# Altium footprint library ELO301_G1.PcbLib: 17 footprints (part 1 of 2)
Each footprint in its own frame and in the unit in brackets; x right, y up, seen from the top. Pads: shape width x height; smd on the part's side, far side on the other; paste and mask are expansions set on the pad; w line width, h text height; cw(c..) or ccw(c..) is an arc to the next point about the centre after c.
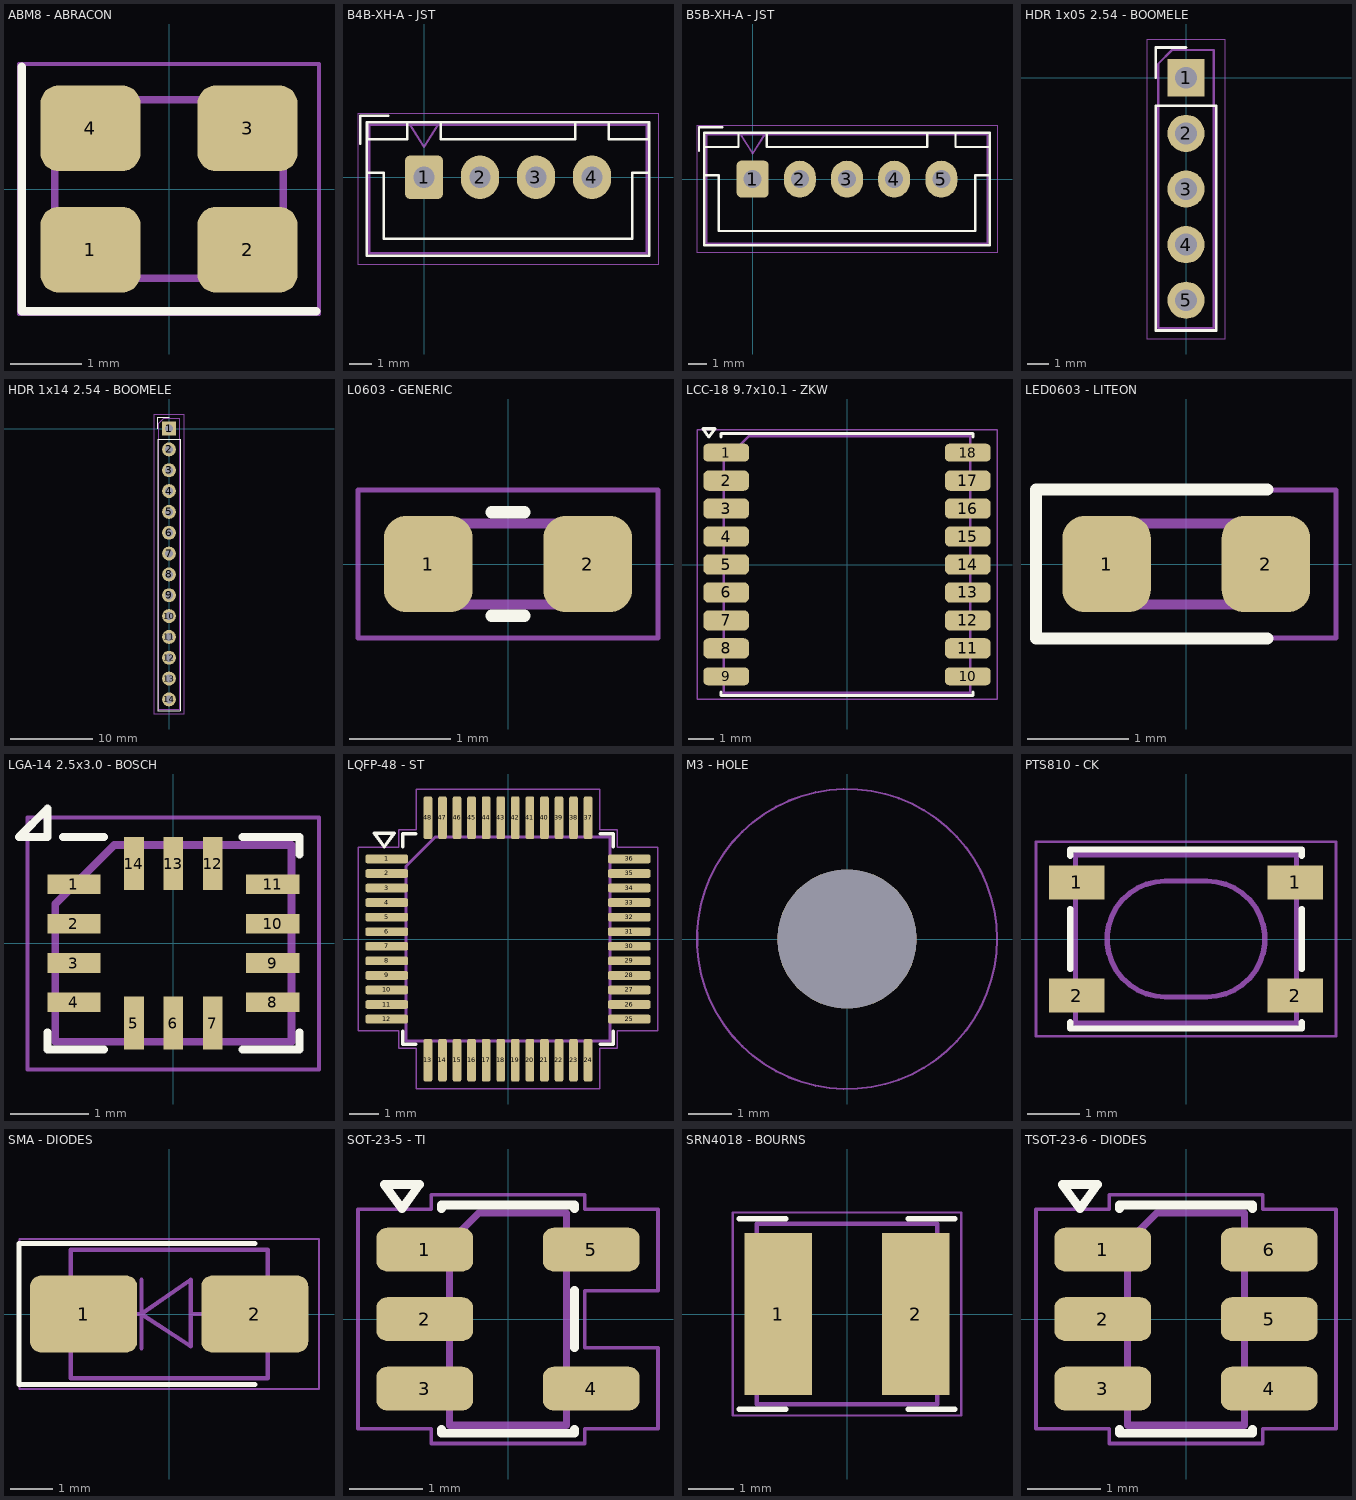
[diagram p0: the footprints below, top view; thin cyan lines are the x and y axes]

## ABM8 - ABRACON [mm] "Abracon ABM8G, Miniature Ceramic Crystal, 3.2x2.5mm package, SMD, http://www.abracon.com/Resonators/ABM8G.pdf"
pads (4):
  rrect42% 1.4x1.2 smd: 1(-1.1,-0.85) 2(1.1,-0.85) 3(1.1,0.85) 4(-1.1,0.85)
Top Overlay:
  lines w0.12: -2.06,1.71 -2.06,-1.71 2.06,-1.71
Mechanical 13:
  lines w0.1: -1.6,-0.625 -0.975,-1.25 1.6,-1.25 1.6,1.25 -1.6,1.25 -1.6,-0.625
Mechanical 15:
  lines w0.05: -2.1,-1.75 2.1,-1.75 2.1,1.75 -2.1,1.75 -2.1,-1.75
Mechanical 29:
  text ".Designator" at -0.508,-0.102 h0.25

## B4B-XH-A - JST [mm] "JST XH series connector, B4B-XH-A (http://www.jst-mfg.com/product/pdf/eng/eXH.pdf)"
pads (4):
  rrect29% 1.7x1.95 hole 0.95: 1(0,0)
  oval 1.7x1.95 hole 0.95: 2(2.5,0) 3(5,0) 4(7.5,0)
Top Overlay:
  lines w0.12: -2.85,1.5 -2.85,2.75 -1.6,2.75 ; -2.55,0.2 -1.8,0.2 -1.8,-2.75 3.75,-2.75 9.3,-2.75 9.3,0.2 10.05,0.2 ; -2.56,-3.51 10.06,-3.51 10.06,2.46 -2.56,2.46 -2.56,-3.51 ; -2.55,1.7 -0.75,1.7 -0.75,2.45 -2.55,2.45 -2.55,1.7 ; 0.75,1.7 6.75,1.7 6.75,2.45 0.75,2.45 0.75,1.7 ; 8.25,1.7 10.05,1.7 10.05,2.45 8.25,2.45 8.25,1.7
Mechanical 13:
  lines w0.1: -0.625,2.35 0,1.35 0.625,2.35 ; -2.45,-3.4 9.95,-3.4 9.95,2.35 -2.45,2.35 -2.45,-3.4
Mechanical 15:
  lines w0.05: -2.95,-3.9 10.45,-3.9 10.45,2.85 -2.95,2.85 -2.95,-3.9
Mechanical 29:
  text ".Designator" at -0.508,-0.102 h0.25

## B5B-XH-A - JST [mm] "JST XH series connector, B5B-XH-A (http://www.jst-mfg.com/product/pdf/eng/eXH.pdf)"
pads (5):
  rrect29% 1.7x1.95 hole 0.95: 1(0,0)
  oval 1.7x1.95 hole 0.95: 2(2.5,0) 3(5,0) 4(7.5,0) 5(10,0)
Top Overlay:
  lines w0.12: -2.85,1.5 -2.85,2.75 -1.6,2.75 ; -2.55,0.2 -1.8,0.2 -1.8,-2.75 5,-2.75 11.8,-2.75 11.8,0.2 12.55,0.2 ; -2.56,-3.51 12.56,-3.51 12.56,2.46 -2.56,2.46 -2.56,-3.51 ; -2.55,1.7 -0.75,1.7 -0.75,2.45 -2.55,2.45 -2.55,1.7 ; 0.75,1.7 9.25,1.7 9.25,2.45 0.75,2.45 0.75,1.7 ; 10.75,1.7 12.55,1.7 12.55,2.45 10.75,2.45 10.75,1.7
Mechanical 13:
  lines w0.1: -0.625,2.35 0,1.35 0.625,2.35 ; -2.45,-3.4 12.45,-3.4 12.45,2.35 -2.45,2.35 -2.45,-3.4
Mechanical 15:
  lines w0.05: -2.95,-3.9 12.95,-3.9 12.95,2.85 -2.95,2.85 -2.95,-3.9
Mechanical 29:
  text ".Designator" at -0.508,-0.102 h0.25

## HDR 1x05 2.54 - BOOMELE [mm] "Through hole straight pin header, 1x05, 2.54mm pitch, single row"
pads (5):
  rect 1.7x1.7 hole 1: 1(0,0)
  round 1.7 hole 1: 2(0,-2.54) 3(0,-5.08) 4(0,-7.62) 5(0,-10.16)
Top Overlay:
  lines w0.12: -1.38,0 -1.38,1.38 0,1.38 ; -1.38,-11.54 -1.38,-1.27 1.38,-1.27 1.38,-11.54 -1.38,-11.54
Mechanical 13:
  lines w0.1: -1.27,-11.43 -1.27,0.635 -0.635,1.27 1.27,1.27 1.27,-11.43 -1.27,-11.43
Mechanical 15:
  lines w0.05: -1.77,-11.93 1.77,-11.93 1.77,1.77 -1.77,1.77 -1.77,-11.93
Mechanical 29:
  text ".Designator" at -0.508,-0.102 h0.25

## HDR 1x14 2.54 - BOOMELE [mm] "Through hole straight pin header, 1x14, 2.54mm pitch, single row"
pads (14):
  rect 1.7x1.7 hole 1: 1(0,0)
  round 1.7 hole 1: 2(0,-2.54) 3(0,-5.08) 4(0,-7.62) 5(0,-10.16) 6(0,-12.7) 7(0,-15.24) 8(0,-17.78) 9(0,-20.32) 10(0,-22.86) 11(0,-25.4) 12(0,-27.94) 13(0,-30.48) 14(0,-33.02)
Top Overlay:
  lines w0.12: -1.38,0 -1.38,1.38 0,1.38 ; -1.38,-34.4 -1.38,-1.27 1.38,-1.27 1.38,-34.4 -1.38,-34.4
Mechanical 13:
  lines w0.1: -1.27,-34.29 -1.27,0.635 -0.635,1.27 1.27,1.27 1.27,-34.29 -1.27,-34.29
Mechanical 15:
  lines w0.05: -1.77,-34.8 1.77,-34.8 1.77,1.78 -1.77,1.78 -1.77,-34.8
Mechanical 29:
  text ".Designator" at -0.508,-0.102 h0.25

## L0603 - GENERIC [mm] "Inductor SMD 0603 (1608 Metric), square (rectangular) end terminal, IPC-7351 nominal, (Body size source: http://www.tortai-tech.com/upload/download/2011102023233369053.pdf)"
pads (2):
  rrect50% 0.875x0.95 smd: 1(-0.788,0) 2(0.788,0)
Top Overlay:
  lines w0.12: -0.163,-0.51 0.163,-0.51 ; -0.163,0.51 0.163,0.51
Mechanical 13:
  lines w0.1: -0.8,-0.4 0.8,-0.4 0.8,0.4 -0.8,0.4 -0.8,-0.4
Mechanical 15:
  lines w0.05: -1.48,-0.73 1.48,-0.73 1.48,0.73 -1.48,0.73 -1.48,-0.73
Mechanical 29:
  text ".Designator" at -0.508,-0.102 h0.25

## LCC-18 9.7x10.1 - ZKW [mm] "ublox MAX 6/7/8, (https://www.u-blox.com/sites/default/files/MAX-8-M8-FW3_HardwareIntegrationManual_%28UBX-15030059%29.pdf)"
pads (18):
  rrect50% 1.8x0.7 smd: 1(-4.75,4.4) 9(-4.75,-4.4) 10(4.75,-4.4) 18(4.75,4.4)
  rrect50% 1.8x0.8 smd: 2(-4.75,3.3) 3(-4.75,2.2) 4(-4.75,1.1) 5(-4.75,0) 6(-4.75,-1.1) 7(-4.75,-2.2) 8(-4.75,-3.3) 11(4.75,-3.3) 12(4.75,-2.2) 13(4.75,-1.1) 14(4.75,0) 15(4.75,1.1) 16(4.75,2.2) 17(4.75,3.3)
Top Overlay:
  lines w0.12: -4.96,-5.01 -4.96,-5.16 4.96,-5.16 4.96,-5.01 ; -4.96,5.01 -4.96,5.16 4.96,5.16 4.96,5.01 ; -5.43,5.01 -5.67,5.34 -5.19,5.34 -5.43,5.01 ; -5.43,5.01 -5.43,5.01
Mechanical 13:
  lines w0.1: -4.85,-5.05 -4.85,4.05 -3.85,5.05 4.85,5.05 4.85,-5.05 -4.85,-5.05
Mechanical 15:
  lines w0.05: -5.9,-5.3 -5.9,5.3 5.9,5.3 5.9,-5.3 -5.9,-5.3
Mechanical 29:
  text ".Designator" at -0.508,-0.102 h0.25

## LED0603 - LITEON [mm] "LED SMD 0603 (1608 Metric), square (rectangular) end terminal, IPC-7351 nominal, (Body size source: http://www.tortai-tech.com/upload/download/2011102023233369053.pdf)"
pads (2):
  rrect50% 0.875x0.95 smd: 1(-0.788,0) 2(0.788,0)
Top Overlay:
  lines w0.12: 0.8,-0.735 -1.485,-0.735 -1.485,0.735 0.8,0.735
Mechanical 13:
  lines w0.1: -0.8,-0.4 -0.8,0.1 -0.5,0.4 0.8,0.4 0.8,-0.4 -0.8,-0.4
Mechanical 15:
  lines w0.05: -1.48,-0.73 1.48,-0.73 1.48,0.73 -1.48,0.73 -1.48,-0.73
Mechanical 29:
  text ".Designator" at -0.508,-0.102 h0.25

## LGA-14 2.5x3.0 - BOSCH [mm] "LGA-14 Bosch https://ae-bst.resource.bosch.com/media/_tech/media/datasheets/BST-BMI160-DS000-07.pdf"
pads (14):
  rect 0.675x0.25 smd: 1(-1.263,0.75) 2(-1.263,0.25) 3(-1.263,-0.25) 4(-1.263,-0.75) 8(1.263,-0.75) 9(1.263,-0.25) 10(1.263,0.25) 11(1.263,0.75)
  rect 0.25x0.675 smd: 5(-0.5,-1.012) 6(0,-1.012) 7(0.5,-1.012) 12(0.5,1.012) 13(0,1.012) 14(-0.5,1.012)
Top Overlay:
  lines w0.1: -1.6,-1.13 -1.6,-1.35 -0.88,-1.35 ; -1.4,1.35 -0.88,1.35 ; 0.88,-1.35 1.6,-1.35 1.6,-1.13 ; 0.88,1.35 1.6,1.35 1.6,1.13 ; -1.6,1.35 -1.96,1.35 -1.6,1.71 -1.6,1.35 ; -1.6,1.35 -1.6,1.35
Mechanical 13:
  lines w0.1: -1.5,-1.25 -1.5,0.5 -0.75,1.25 1.5,1.25 1.5,-1.25 -1.5,-1.25
Mechanical 15:
  lines w0.05: -1.85,-1.6 -1.85,1.6 1.85,1.6 1.85,-1.6 -1.85,-1.6
Mechanical 29:
  text ".Designator" at -0.508,-0.102 h0.25

## LQFP-48 - ST [mm] "LQFP, 48 Pin (JEDEC MS-026 variation BBC, 1.40mm body thickness, https://www.jedec.org/document_search?search_api_views_fulltext=MS-026, https://www.analog.com/media/en/package-pcb-resources/package/pkg_pdf/ltc-legacy-lqfp/05081760_a_lx48.pdf)"
pads (48):
  rrect50% 1.475x0.3 smd: 1(-4.163,2.75) 2(-4.163,2.25) 3(-4.163,1.75) 4(-4.163,1.25) 5(-4.163,0.75) 6(-4.163,0.25) 7(-4.163,-0.25) 8(-4.163,-0.75) 9(-4.163,-1.25) 10(-4.163,-1.75) 11(-4.163,-2.25) 12(-4.163,-2.75) 25(4.163,-2.75) 26(4.163,-2.25) 27(4.163,-1.75) 28(4.163,-1.25) 29(4.163,-0.75) 30(4.163,-0.25) 31(4.163,0.25) 32(4.163,0.75) 33(4.163,1.25) 34(4.163,1.75) 35(4.163,2.25) 36(4.163,2.75)
  rrect50% 0.3x1.475 smd: 13(-2.75,-4.163) 14(-2.25,-4.163) 15(-1.75,-4.163) 16(-1.25,-4.163) 17(-0.75,-4.163) 18(-0.25,-4.163) 19(0.25,-4.163) 20(0.75,-4.163) 21(1.25,-4.163) 22(1.75,-4.163) 23(2.25,-4.163) 24(2.75,-4.163) 37(2.75,4.163) 38(2.25,4.163) 39(1.75,4.163) 40(1.25,4.163) 41(0.75,4.163) 42(0.25,4.163) 43(-0.25,4.163) 44(-0.75,4.163) 45(-1.25,4.163) 46(-1.75,4.163) 47(-2.25,4.163) 48(-2.75,4.163)
Top Overlay:
  lines w0.12: -3.61,-3.16 -3.61,-3.61 -3.16,-3.61 ; -3.61,3.16 -3.61,3.61 -3.16,3.61 ; 3.16,-3.61 3.61,-3.61 3.61,-3.16 ; 3.16,3.61 3.61,3.61 3.61,3.16 ; -4.59,3.63 -4.25,3.16 -3.91,3.63 -4.59,3.63
Mechanical 13:
  lines w0.1: -3.5,-3.5 3.5,-3.5 3.5,3.5 -2.5,3.5 -3.5,2.5 -3.5,-3.5
Mechanical 15:
  lines w0.05: -5.15,-3.15 -5.15,3.15 -3.75,3.15 -3.75,3.75 -3.15,3.75 -3.15,5.15 3.15,5.15 3.15,3.75 3.75,3.75 3.75,3.15 5.15,3.15 5.15,-3.15 3.75,-3.15 3.75,-3.75 3.15,-3.75 3.15,-5.15 -3.15,-5.15 -3.15,-3.75 -3.75,-3.75 -3.75,-3.15 -5.15,-3.15
Mechanical 29:
  text ".Designator" at -0.508,-0.102 h0.25

## M3 - HOLE [mm] "Mounting Hole 3.2mm, M3, no annular, generated by kicad-footprint-generator mountinghole.py"
pads (1):
  round 3.2 hole 3.2 unplated: ""(0,0)
Mechanical 15:
  circle w0.05: c0,0 r3.45
Mechanical 29:
  text ".Designator" at -0.508,-0.102 h0.25

## PTS810 - CK [mm] "C&K Components, PTS 810 Series, Microminiature SMT Top Actuated, http://www.ckswitches.com/media/1476/pts810.pdf"
pads (4):
  rect 1.05x0.65 smd: 1(-2.075,1.075) 1(2.075,1.075) 2(-2.075,-1.075) 2(2.075,-1.075)
Top Overlay:
  lines w0.12: -2.2,-1.58 -2.2,-1.7 2.2,-1.7 2.2,-1.58 ; -2.2,-0.57 -2.2,0.57 ; -2.2,1.58 -2.2,1.7 2.2,1.7 2.2,1.58 ; 2.2,-0.57 2.2,0.57
Mechanical 13:
  lines w0.1: -2.1,-1.6 -2.1,1.6 2.1,1.6 2.1,-1.6 -2.1,-1.6 ; -0.4,-1.1 0.4,-1.1 ccw(c0.4,0) 0.4,1.1 -0.4,1.1 ccw(c-0.4,0) -0.4,-1.1
Mechanical 15:
  lines w0.05: -2.85,-1.85 -2.85,1.85 2.85,1.85 2.85,-1.85 -2.85,-1.85
Mechanical 29:
  text ".Designator" at -0.508,-0.102 h0.25

## SMA - DIODES [mm] "Diode SMA (DO-214AC)"
pads (2):
  rrect28% 2.5x1.8 smd: 1(-2,0) 2(2,0)
Top Overlay:
  lines w0.12: 2,-1.65 -3.51,-1.65 -3.51,1.65 2,1.65
Mechanical 13:
  lines w0.1: -1.551,-0.001 -0.649,-0.001 ; -0.649,-0.801 -0.649,0.799 ; 0.501,-0.001 1.499,-0.001 ; -0.649,-0.001 0.501,0.799 0.501,-0.75 -0.649,-0.001 ; -2.3,-1.5 -2.3,1.5 2.3,1.5 2.3,-1.5 -2.3,-1.5
Mechanical 15:
  lines w0.05: -3.5,-1.75 -3.5,1.75 3.5,1.75 3.5,-1.75 -3.5,-1.75
Mechanical 29:
  text ".Designator" at -0.508,-0.102 h0.25

## SOT-23-5 - TI [mm] "SOT, 5 Pin (JEDEC MO-178 Var AA https://www.jedec.org/document_search?search_api_views_fulltext=MO-178)"
pads (5):
  rrect50% 1.325x0.6 smd: 1(-1.137,0.95) 2(-1.137,0) 3(-1.137,-0.95) 4(1.137,-0.95) 5(1.137,0.95)
Top Overlay:
  lines w0.12: -0.91,-1.51 -0.91,-1.56 0.91,-1.56 0.91,-1.51 ; -0.91,1.51 -0.91,1.56 0.91,1.56 0.91,1.51 ; 0.91,-0.39 0.91,0.39 ; -1.69,1.84 -1.45,1.51 -1.21,1.84 -1.69,1.84
Mechanical 13:
  lines w0.1: -0.8,-1.45 0.8,-1.45 0.8,1.45 -0.4,1.45 -0.8,1.05 -0.8,-1.45
Mechanical 15:
  lines w0.05: -2.05,-1.5 -2.05,1.5 -1.05,1.5 -1.05,1.7 1.05,1.7 1.05,1.5 2.05,1.5 2.05,0.39 1.05,0.39 1.05,-0.39 2.05,-0.39 2.05,-1.5 1.05,-1.5 1.05,-1.7 -1.05,-1.7 -1.05,-1.5 -2.05,-1.5
Mechanical 29:
  text ".Designator" at -0.508,-0.102 h0.25

## SRN4018 - BOURNS [mm] "Bourns SRN4018 series SMD inductor, https://www.bourns.com/docs/Product-Datasheets/SRN4018.pdf"
pads (2):
  rect 1.5x3.6 smd: 1(-1.525,0) 2(1.525,0)
Top Overlay:
  lines w0.12: -2.385,-2.11 -1.36,-2.11 ; -2.385,2.11 -1.36,2.11 ; 1.36,-2.11 2.385,-2.11 ; 1.36,2.11 2.385,2.11
Mechanical 13:
  lines w0.1: -2,-2 -2,2 2,2 2,-2 -2,-2
Mechanical 15:
  lines w0.05: -2.53,-2.25 -2.53,2.25 2.53,2.25 2.53,-2.25 -2.53,-2.25
Mechanical 29:
  text ".Designator" at -0.508,-0.102 h0.25

## TSOT-23-6 - DIODES [mm] "TSOT, 6 Pin (https://www.jedec.org/sites/default/files/docs/MO-193D.pdf variant AA)"
pads (6):
  rrect50% 1.325x0.6 smd: 1(-1.137,0.95) 2(-1.137,0) 3(-1.137,-0.95) 4(1.137,-0.95) 5(1.137,0) 6(1.137,0.95)
Top Overlay:
  lines w0.12: -0.91,-1.51 -0.91,-1.56 0.91,-1.56 0.91,-1.51 ; -0.91,1.51 -0.91,1.56 0.91,1.56 0.91,1.51 ; -1.69,1.84 -1.45,1.51 -1.21,1.84 -1.69,1.84
Mechanical 13:
  lines w0.1: -0.8,-1.45 0.8,-1.45 0.8,1.45 -0.4,1.45 -0.8,1.05 -0.8,-1.45
Mechanical 15:
  lines w0.05: -2.05,-1.5 -2.05,1.5 -1.05,1.5 -1.05,1.7 1.05,1.7 1.05,1.5 2.05,1.5 2.05,-1.5 1.05,-1.5 1.05,-1.7 -1.05,-1.7 -1.05,-1.5 -2.05,-1.5
Mechanical 29:
  text ".Designator" at -0.508,-0.102 h0.25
